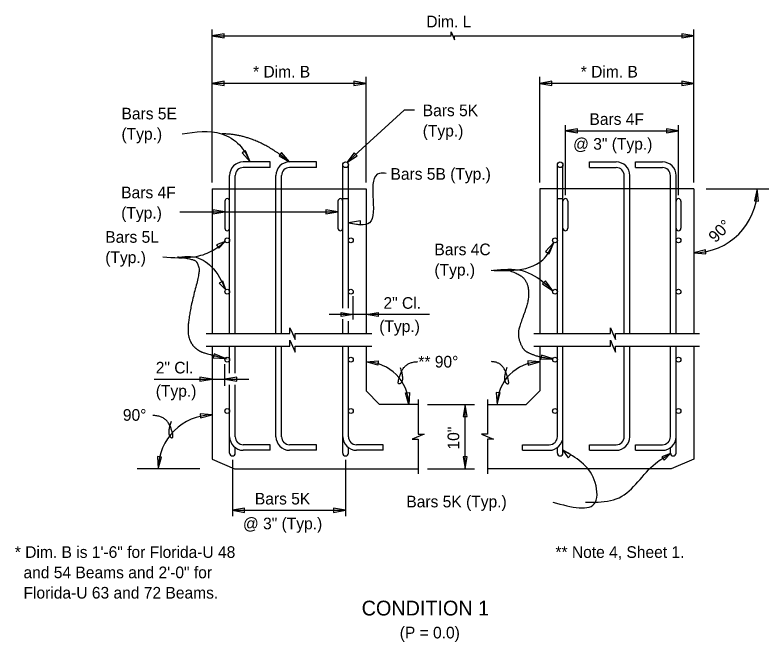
# Model space of a CAD drawing. Extents: x 0.5 to 29.5, y 0.9 to 17.7.
# Drawn here: x 0.5 to 10.29, y 9.57 to 17.7 of the extents above; entities that cross this region are included whole.
import ezdxf

# ---------------------------------------------------------------- set-up
doc = ezdxf.new("R2010")
doc.units = 0
for name, color, linetype in [('BeamConc', 7, 'Continuous'), ('Dimension', 7, 'Continuous'), ('Rebar', 7, 'Continuous'), ('TextStructures', 7, 'Continuous')]:
    doc.layers.add(name, color=color, linetype=linetype)

# ---------------------------------------------------------------- blocks, each defined once
blk = doc.blocks.new('Terminator-Arrow')
at = {"layer": 'Dimension'}
blk.add_lwpolyline([(0, 0), (-0.00041, 0.000069), (-0.00041, -0.000069)], close=True, dxfattribs=at)

msp = doc.modelspace()

# ---------------------------------------------------------------- linework, layer by layer
at = {"layer": 'BeamConc'}
for p, q in [((3.0596, 15.4467), (3.0596, 13.5686)), ((3.0597, 15.4467), (5.0597, 15.4467)), ((5.0597, 15.4467), (5.0597, 13.5686)), ((9.3147, 15.4467), (7.3147, 15.4467)), ((7.3147, 15.4467), (7.3147, 13.5686)), ((9.3146, 15.4467), (9.3146, 13.5686)), ((3.0596, 13.4069), (3.0596, 11.9397)), ((5.0597, 13.4069), (5.0597, 12.8248)), ((7.3147, 13.4069), (7.3147, 12.8248)), ((9.3146, 13.4069), (9.3146, 11.9397)), ((5.2364, 12.648), (5.0597, 12.8248)), ((7.1379, 12.648), (7.3147, 12.8248)), ((5.737, 12.648), (5.2364, 12.648)), ((6.6373, 12.648), (7.1379, 12.648)), ((3.0596, 11.9397), (3.3513, 11.8147)), ((9.3146, 11.9397), (9.023, 11.8147)), ((3.3513, 11.8147), (5.737, 11.8147)), ((9.023, 11.8147), (6.6373, 11.8147))]:
    msp.add_line(p, q, dxfattribs=at)
at = {"layer": 'Dimension'}
for p, q in [((3.0597, 15.5294), (3.0597, 17.5191)), ((3.0597, 15.5294), (3.0597, 17.5191)), ((9.3147, 15.5294), (9.3147, 17.5191)), ((9.3147, 15.5294), (9.3147, 17.5191)), ((5.0597, 15.5294), (5.0597, 16.9032)), ((5.0597, 15.5294), (5.0597, 16.9032)), ((7.3146, 15.5294), (7.3146, 16.9032)), ((7.3146, 15.5294), (7.3146, 16.9032)), ((3.0595, 16.8187), (5.0595, 16.8187)), ((3.0595, 16.8187), (5.0595, 16.8187)), ((7.3146, 16.8187), (9.3146, 16.8187)), ((7.3146, 16.8187), (9.3146, 16.8187)), ((7.648, 15.3678), (7.648, 16.2742)), ((7.648, 15.3678), (7.648, 16.2742)), ((9.1167, 15.3678), (9.1167, 16.2742)), ((9.1167, 15.3678), (9.1167, 16.2742)), ((7.648, 16.2036), (9.1167, 16.2036)), ((7.648, 16.2036), (9.1167, 16.2036)), ((9.4776, 15.4467), (10.2909, 15.4467)), ((9.4776, 15.4467), (10.2909, 15.4467)), ((2.6412, 15.1505), (3.2263, 15.1505)), ((2.6412, 15.1505), (3.2263, 15.1505)), ((3.2263, 15.1505), (4.6951, 15.1505)), ((3.2263, 15.1505), (4.6951, 15.1505)), ((4.893, 13.7541), (4.893, 14.0544)), ((4.893, 13.7541), (4.893, 14.0544)), ((5.8819, 13.8162), (4.5829, 13.8162)), ((5.8819, 13.8162), (4.5829, 13.8162)), ((3.2263, 12.8915), (3.2263, 13.1747)), ((3.2263, 12.8915), (3.2263, 13.1747)), ((2.3102, 12.9769), (3.5364, 12.9769)), ((2.3102, 12.9769), (3.5364, 12.9769)), ((5.8581, 12.648), (6.4662, 12.648)), ((5.8581, 12.648), (6.4662, 12.648)), ((6.3454, 11.8147), (6.3454, 12.648)), ((6.3454, 11.8147), (6.3454, 12.648)), ((3.3253, 11.932), (3.3253, 11.2001)), ((3.3253, 11.932), (3.3253, 11.2001)), ((4.794, 11.932), (4.794, 11.2001)), ((4.794, 11.932), (4.794, 11.2001)), ((2.9018, 11.8147), (2.0885, 11.8147)), ((2.9018, 11.8147), (2.0885, 11.8147)), ((5.8581, 11.8147), (6.4662, 11.8147)), ((5.8581, 11.8147), (6.4662, 11.8147)), ((3.3253, 11.2757), (4.794, 11.2757)), ((3.3253, 11.2757), (4.794, 11.2757))]:
    msp.add_line(p, q, dxfattribs=at)
for points in [[(3.0595, 17.434), (6.1645, 17.434), (6.1645, 17.4857), (6.187, 17.434), (6.2095, 17.3823), (6.2095, 17.434), (9.3145, 17.434)], [(3.0595, 17.434), (6.1645, 17.434), (6.1645, 17.4857), (6.187, 17.434), (6.2095, 17.3823), (6.2095, 17.434), (9.3145, 17.434)], [(5.687, 16.4694), (5.554, 16.4694), (4.8092, 15.7907)], [(5.687, 16.4694), (5.554, 16.4694), (4.8092, 15.7907)], [(2.984, 13.5686), (4.0719, 13.5686), (4.0719, 13.6461), (4.1056, 13.5686), (4.1394, 13.4911), (4.1394, 13.5686), (5.1353, 13.5686)], [(2.984, 13.5686), (4.0719, 13.5686), (4.0719, 13.6461), (4.1056, 13.5686), (4.1394, 13.4911), (4.1394, 13.5686), (5.1353, 13.5686)], [(7.239, 13.5686), (8.2317, 13.5686), (8.2317, 13.6461), (8.2655, 13.5686), (8.2992, 13.4911), (8.2992, 13.5686), (9.3903, 13.5686)], [(7.239, 13.5686), (8.2317, 13.5686), (8.2317, 13.6461), (8.2655, 13.5686), (8.2992, 13.4911), (8.2992, 13.5686), (9.3903, 13.5686)], [(2.984, 13.4069), (4.0719, 13.4069), (4.0719, 13.4844), (4.1056, 13.4069), (4.1394, 13.3294), (4.1394, 13.4069), (5.1353, 13.4069)], [(2.984, 13.4069), (4.0719, 13.4069), (4.0719, 13.4844), (4.1056, 13.4069), (4.1394, 13.3294), (4.1394, 13.4069), (5.1353, 13.4069)], [(7.239, 13.4069), (8.2317, 13.4069), (8.2317, 13.4844), (8.2655, 13.4069), (8.2992, 13.3294), (8.2992, 13.4069), (9.3903, 13.4069)], [(7.239, 13.4069), (8.2317, 13.4069), (8.2317, 13.4844), (8.2655, 13.4069), (8.2992, 13.3294), (8.2992, 13.4069), (9.3903, 13.4069)], [(5.737, 12.7151), (5.737, 12.2651), (5.8145, 12.2651), (5.6595, 12.1976), (5.737, 12.1976), (5.737, 11.7476)], [(5.737, 12.7151), (5.737, 12.2651), (5.8145, 12.2651), (5.6595, 12.1976), (5.737, 12.1976), (5.737, 11.7476)], [(6.6373, 12.7151), (6.6373, 12.2651), (6.5598, 12.2651), (6.7148, 12.1976), (6.6373, 12.1976), (6.6373, 11.7476)], [(6.6373, 12.7151), (6.6373, 12.2651), (6.5598, 12.2651), (6.7148, 12.1976), (6.6373, 12.1976), (6.6373, 11.7476)]]:
    msp.add_lwpolyline(points, dxfattribs=at)
for points in [[(3.5569, 15.7974), (3.4949, 15.9432), (3.4504, 15.9146)], [(3.5569, 15.7974), (3.4949, 15.9432), (3.4504, 15.9146)], [(4.0668, 15.798), (3.9638, 15.9184), (3.9299, 15.8777)], [(4.0668, 15.798), (3.9638, 15.9184), (3.9299, 15.8777)], [(4.8092, 15.7908), (4.9425, 15.8764), (4.9069, 15.9155)], [(4.8092, 15.7908), (4.9425, 15.8764), (4.9069, 15.9155)], [(10.14, 15.4467), (10.1018, 15.293), (10.1546, 15.289)], [(10.14, 15.4467), (10.1018, 15.293), (10.1546, 15.289)], [(3.2263, 15.1505), (3.0701, 15.177), (3.0701, 15.1241)], [(3.2263, 15.1505), (3.0701, 15.177), (3.0701, 15.1241)], [(4.6951, 15.1505), (4.5389, 15.177), (4.5389, 15.1241)], [(4.6951, 15.1505), (4.5389, 15.177), (4.5389, 15.1241)], [(4.8305, 15.0073), (4.9867, 14.9809), (4.9867, 15.0338)], [(4.8305, 15.0073), (4.9867, 14.9809), (4.9867, 15.0338)], [(3.2294, 14.7665), (3.1187, 14.7199), (3.1495, 14.6768)], [(3.2294, 14.7665), (3.1187, 14.7199), (3.1495, 14.6768)], [(7.496, 14.7535), (7.3906, 14.6352), (7.4355, 14.6071)], [(7.496, 14.7535), (7.3906, 14.6352), (7.4355, 14.6071)], [(9.3147, 14.6188), (9.4725, 14.6058), (9.468, 14.6585)], [(9.3147, 14.6188), (9.4725, 14.6058), (9.468, 14.6585)], [(3.238, 14.1377), (3.1988, 14.2512), (3.1538, 14.2233)], [(3.238, 14.1377), (3.1988, 14.2512), (3.1538, 14.2233)], [(7.4844, 14.1268), (7.3891, 14.2534), (7.3528, 14.215)], [(7.4844, 14.1268), (7.3891, 14.2534), (7.3528, 14.215)], [(3.2344, 13.2478), (3.0868, 13.3051), (3.0761, 13.2533)], [(3.2344, 13.2478), (3.0868, 13.3051), (3.0761, 13.2533)], [(5.0597, 13.2014), (5.2175, 13.2145), (5.213, 13.1617)], [(5.0597, 13.2014), (5.2175, 13.2145), (5.213, 13.1617)], [(7.3168, 13.2014), (7.1589, 13.2145), (7.1634, 13.1617)], [(7.3168, 13.2014), (7.1589, 13.2145), (7.1634, 13.1617)], [(7.4882, 13.2403), (7.3371, 13.2881), (7.3299, 13.2356)], [(7.4882, 13.2403), (7.3371, 13.2881), (7.3299, 13.2356)], [(5.6144, 12.6461), (5.5733, 12.7991), (5.626, 12.8041)], [(5.6144, 12.6461), (5.5733, 12.7991), (5.626, 12.8041)], [(6.762, 12.6461), (6.8032, 12.7991), (6.7505, 12.8041)], [(6.762, 12.6461), (6.8032, 12.7991), (6.7505, 12.8041)], [(6.3454, 12.648), (6.319, 12.4918), (6.3719, 12.4918)], [(6.3454, 12.648), (6.319, 12.4918), (6.3719, 12.4918)], [(3.0617, 12.5144), (2.9039, 12.5275), (2.9084, 12.4748)], [(3.0617, 12.5144), (2.9039, 12.5275), (2.9084, 12.4748)], [(7.6167, 12.0573), (7.6836, 11.9576), (7.72, 11.996)], [(7.6167, 12.0573), (7.6836, 11.9576), (7.72, 11.996)], [(2.3623, 11.8144), (2.4034, 11.9674), (2.3507, 11.9724)], [(2.3623, 11.8144), (2.4034, 11.9674), (2.3507, 11.9724)], [(6.3454, 11.8147), (6.3719, 11.9709), (6.319, 11.9709)], [(6.3454, 11.8147), (6.3719, 11.9709), (6.319, 11.9709)], [(9.0132, 12.0113), (8.9006, 11.9696), (8.9294, 11.9252)], [(9.0132, 12.0113), (8.9006, 11.9696), (8.9294, 11.9252)]]:
    msp.add_lwpolyline(points, close=True, dxfattribs=at)
for centre, radius, start, end in [((9.3121, 15.4467), 0.8279, 270.17686, 0), ((9.3121, 15.4467), 0.8279, 270.17686, 0), ((5.0553, 12.6422), 0.5592, 0.39914, 89.54996), ((5.0553, 12.6422), 0.5592, 0.39914, 89.54996), ((7.3212, 12.6422), 0.5592, 90.45004, 179.60086), ((7.3212, 12.6422), 0.5592, 90.45004, 179.60086), ((3.0673, 11.8094), 0.705, 90.45004, 179.60086), ((3.0673, 11.8094), 0.705, 90.45004, 179.60086)]:
    msp.add_arc(centre, radius, start, end, dxfattribs=at)
for points in [[(2.67, 16.162), (3.1844, 16.162), (3.4145, 16.0195), (3.5569, 15.7974)], [(2.67, 16.162), (3.1844, 16.162), (3.4145, 16.0195), (3.5569, 15.7974)], [(5.3202, 15.6496), (5.2362, 15.6496), (5.1038, 15.0073), (4.8305, 15.0073)], [(5.3202, 15.6496), (5.2362, 15.6496), (5.1038, 15.0073), (4.8305, 15.0073)], [(2.4221, 14.5672), (2.831, 14.5672), (3.0502, 14.6385), (3.2294, 14.7665)], [(2.4221, 14.5672), (2.831, 14.5672), (3.0502, 14.6385), (3.2294, 14.7665)], [(6.686, 14.3917), (6.9806, 14.3917), (7.3535, 14.526), (7.496, 14.7535)], [(6.686, 14.3917), (6.9806, 14.3917), (7.3535, 14.526), (7.496, 14.7535)], [(2.6667, 14.5672), (2.8201, 14.5672), (3.0502, 14.4411), (3.238, 14.1377)], [(2.6667, 14.5672), (2.8201, 14.5672), (3.0502, 14.4411), (3.238, 14.1377)], [(6.7146, 14.3917), (7.085, 14.3867), (7.3858, 14.2201), (7.4844, 14.1268)], [(6.7146, 14.3917), (7.085, 14.3867), (7.3858, 14.2201), (7.4844, 14.1268)], [(7.4869, 11.3802), (8.0377, 11.3809), (8.023, 11.6725), (7.6167, 12.0573)], [(7.4869, 11.3802), (8.0377, 11.3809), (8.023, 11.6725), (7.6167, 12.0573)], [(7.9078, 11.3808), (8.0326, 11.3809), (8.3444, 11.4388), (8.8193, 11.8852), (9.0132, 12.0112)], [(7.9078, 11.3808), (8.0326, 11.3809), (8.3444, 11.4388), (8.8193, 11.8852), (9.0132, 12.0112)]]:
    msp.add_spline(points, degree=3, dxfattribs=at)
for points in [[(4.0669, 15.7974), (3.6296, 16.1619), (3.1923, 16.1619)], [(4.0669, 15.7974), (3.6296, 16.1619), (3.1923, 16.1619)], [(2.6102, 14.5672), (2.8249, 14.5347), (2.8713, 14.4882), (2.9054, 14.3766), (2.7877, 13.952), (2.735, 13.5893), (2.7877, 13.4344), (2.8899, 13.3414), (3.0045, 13.3042), (3.2556, 13.2403)], [(2.6102, 14.5672), (2.8249, 14.5347), (2.8713, 14.4882), (2.9054, 14.3766), (2.7877, 13.952), (2.735, 13.5893), (2.7877, 13.4344), (2.8899, 13.3414), (3.0045, 13.3042), (3.2556, 13.2403)], [(6.9141, 14.389), (7.0804, 14.3358), (7.1708, 14.193), (7.1708, 13.9885), (7.0757, 13.7316), (7.0234, 13.5603), (7.0852, 13.3842), (7.147, 13.3272), (7.3087, 13.2653), (7.4882, 13.2403)], [(6.9141, 14.389), (7.0804, 14.3358), (7.1708, 14.193), (7.1708, 13.9885), (7.0757, 13.7316), (7.0234, 13.5603), (7.0852, 13.3842), (7.147, 13.3272), (7.3087, 13.2653), (7.4882, 13.2403)], [(5.5035, 13.1287), (5.5608, 12.9568), (5.45, 12.8881), (5.5627, 13.2051), (5.7343, 13.2051)], [(5.5035, 13.1287), (5.5608, 12.9568), (5.45, 12.8881), (5.5627, 13.2051), (5.7343, 13.2051)], [(6.8868, 13.1287), (6.8295, 12.9568), (6.9403, 12.8881), (6.8276, 13.2051), (6.688, 13.2051)], [(6.8868, 13.1287), (6.8295, 12.9568), (6.9403, 12.8881), (6.8276, 13.2051), (6.688, 13.2051)], [(2.5274, 12.4294), (2.4701, 12.2575), (2.5808, 12.1887), (2.4682, 12.5058), (2.2906, 12.5058)], [(2.5274, 12.4294), (2.4701, 12.2575), (2.5808, 12.1887), (2.4682, 12.5058), (2.2906, 12.5058)]]:
    msp.add_open_spline(points, degree=2, dxfattribs=at)
at = {"layer": 'Rebar'}
for p, q in [((3.8138, 15.7974), (3.466, 15.7974)), ((3.8138, 15.7245), (3.8138, 15.7974)), ((4.4148, 15.7974), (4.0669, 15.7974)), ((4.4148, 15.7245), (4.4148, 15.7974)), ((4.7576, 13.9017), (4.7576, 15.7609)), ((4.8305, 13.9017), (4.8305, 15.7609)), ((7.5438, 13.5686), (7.5438, 15.7609)), ((7.6167, 13.5686), (7.6167, 15.7609)), ((7.9604, 15.7974), (8.3083, 15.7974)), ((7.9604, 15.7245), (7.9604, 15.7974)), ((8.5605, 15.7974), (8.9084, 15.7974)), ((8.5605, 15.7245), (8.5605, 15.7974)), ((3.8138, 15.7245), (3.466, 15.7245)), ((4.4148, 15.7245), (4.0669, 15.7245)), ((7.9604, 15.7245), (8.3083, 15.7245)), ((8.5605, 15.7245), (8.9084, 15.7245)), ((3.2888, 13.5686), (3.2888, 15.6203)), ((3.3618, 13.5686), (3.3618, 15.6203)), ((3.8898, 13.5686), (3.8898, 15.6203)), ((3.9627, 13.5686), (3.9627, 15.6203)), ((8.4125, 13.5686), (8.4125, 15.6203)), ((8.4854, 13.5686), (8.4854, 15.6203)), ((9.0126, 13.5686), (9.0126, 15.6203)), ((9.0855, 13.5686), (9.0855, 15.6203)), ((3.2263, 15.2904), (3.2263, 14.9363)), ((4.6951, 15.2904), (4.6951, 14.9363)), ((4.7576, 15.3217), (4.8305, 15.3217)), ((7.5438, 15.3217), (7.6167, 15.3217)), ((7.6792, 15.2904), (7.6792, 14.9363)), ((9.148, 15.2904), (9.148, 14.9363)), ((4.7576, 13.5686), (4.7576, 13.755)), ((4.8305, 13.5686), (4.8305, 13.7326)), ((3.2888, 13.056), (3.2888, 13.4069)), ((3.3618, 13.056), (3.3618, 13.4069)), ((3.8898, 12.2313), (3.8898, 13.4069)), ((3.9627, 12.2314), (3.9627, 13.4069)), ((4.7576, 12.0178), (4.7576, 13.4069)), ((4.8305, 12.2313), (4.8305, 13.4069)), ((7.5438, 12.2313), (7.5438, 13.4069)), ((7.6167, 12.0178), (7.6167, 13.4069)), ((8.4125, 12.2314), (8.4125, 13.4069)), ((8.4854, 12.2313), (8.4854, 13.4069)), ((9.0126, 12.2313), (9.0126, 13.4069)), ((9.0855, 12.0178), (9.0855, 13.4069)), ((3.2888, 12.0178), (3.2888, 12.9035)), ((3.3618, 12.2313), (3.3618, 12.9035)), ((3.3618, 12.0178), (3.3618, 12.0881)), ((3.8138, 12.1271), (3.466, 12.1271)), ((3.8138, 12.0542), (3.466, 12.0542)), ((3.8138, 12.0542), (3.8138, 12.1271)), ((4.4148, 12.1271), (4.0669, 12.1271)), ((4.4148, 12.0542), (4.0669, 12.0542)), ((4.4148, 12.0542), (4.4148, 12.1271)), ((4.8305, 12.0178), (4.8305, 12.0881)), ((5.2826, 12.1271), (4.9347, 12.1271)), ((5.2826, 12.0542), (4.9347, 12.0542)), ((5.2826, 12.0542), (5.2826, 12.1271)), ((7.0917, 12.1271), (7.4396, 12.1271)), ((7.0917, 12.0542), (7.0917, 12.1271)), ((7.0917, 12.0542), (7.4396, 12.0542)), ((7.5438, 12.0178), (7.5438, 12.0881)), ((7.9604, 12.1271), (8.3083, 12.1271)), ((7.9604, 12.0542), (7.9604, 12.1271)), ((7.9604, 12.0542), (8.3083, 12.0542)), ((8.5605, 12.1271), (8.9084, 12.1271)), ((8.5605, 12.0542), (8.5605, 12.1271)), ((8.5605, 12.0542), (8.9084, 12.0542)), ((9.0126, 12.0178), (9.0126, 12.0881))]:
    msp.add_line(p, q, dxfattribs=at)
for centre, radius in [((4.794, 15.7609), 0.0365), ((7.5803, 15.7609), 0.0365), ((3.2576, 14.78), 0.0312), ((4.8618, 14.78), 0.0312), ((7.5126, 14.78), 0.0312), ((9.1167, 14.78), 0.0312), ((3.2576, 14.1133), 0.0312), ((4.8618, 14.1133), 0.0312), ((7.5126, 14.1133), 0.0312), ((9.1167, 14.1133), 0.0312), ((3.2576, 13.2313), 0.0312), ((4.8618, 13.2313), 0.0312), ((7.5126, 13.2313), 0.0312), ((9.1167, 13.2313), 0.0312), ((3.2576, 12.5646), 0.0312), ((4.8618, 12.5646), 0.0312), ((7.5126, 12.5646), 0.0312), ((9.1167, 12.5646), 0.0312)]:
    msp.add_circle(centre, radius, dxfattribs=at)
for centre, radius, start, end in [((3.466, 15.6203), 0.1771, 90, 180), ((4.0669, 15.6203), 0.1771, 90, 180), ((8.3083, 15.6203), 0.1771, 0, 90), ((8.9084, 15.6203), 0.1771, 0, 90), ((3.466, 15.6203), 0.1042, 90, 180), ((4.0669, 15.6203), 0.1042, 90, 180), ((8.3083, 15.6203), 0.1042, 0, 90), ((8.9084, 15.6203), 0.1042, 0, 90), ((3.2576, 15.2904), 0.0312, 0, 180), ((4.7263, 15.2904), 0.0312, 0, 180), ((7.648, 15.2904), 0.0312, 0, 180), ((9.1167, 15.2904), 0.0312, 0, 180), ((3.2576, 14.9363), 0.0312, 180, 0), ((4.7263, 14.9363), 0.0312, 180, 0), ((7.648, 14.9363), 0.0312, 180, 0), ((9.1167, 14.9363), 0.0312, 180, 0), ((3.466, 12.2313), 0.1771, 180, 270), ((3.466, 12.2313), 0.1042, 180, 270), ((4.0669, 12.2313), 0.1771, 180, 270), ((4.0669, 12.2313), 0.1042, 180, 270), ((4.9347, 12.2313), 0.1771, 180, 270), ((4.9347, 12.2313), 0.1042, 180, 270), ((7.4396, 12.2313), 0.1042, 270, 360), ((7.4396, 12.2313), 0.1771, 270, 360), ((8.3083, 12.2313), 0.1042, 270, 0), ((8.3083, 12.2313), 0.1771, 270, 0), ((8.9084, 12.2313), 0.1042, 270, 360), ((8.9084, 12.2313), 0.1771, 270, 360), ((3.3253, 12.0178), 0.0365, 180, 0), ((4.794, 12.0178), 0.0365, 180, 0), ((7.5803, 12.0178), 0.0365, 180, 0), ((9.049, 12.0178), 0.0365, 180, 0)]:
    msp.add_arc(centre, radius, start, end, dxfattribs=at)

# ---------------------------------------------------------------- block references
at = {"layer": 'Dimension', "xscale": 381, "rotation": 180}
for p, yscale in [((3.0594, 17.4335), 384.0238095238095), ((3.0594, 17.4335), 384.0238095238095), ((3.0594, 16.8183), 384.0238095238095), ((3.0594, 16.8183), 384.0238095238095), ((7.3144, 16.8183), 384.0238095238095), ((7.3144, 16.8183), 384.0238095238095), ((7.6478, 16.2033), 384.0238095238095), ((7.6478, 16.2033), 384.0238095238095), ((5.0596, 13.8159), -384.0238095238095), ((5.0596, 13.8159), -384.0238095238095), ((3.2262, 12.9764), 384.0238095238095), ((3.2262, 12.9764), 384.0238095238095), ((3.3252, 11.2754), 384.0238095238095), ((3.3252, 11.2754), 384.0238095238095)]:
    msp.add_blockref('Terminator-Arrow', p, dxfattribs=dict(at, yscale=yscale))
at = {"layer": 'Dimension', "xscale": 381}
for p, yscale in [((9.3144, 17.4336), 384.0238095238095), ((9.3144, 17.4336), 384.0238095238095), ((5.0594, 16.8183), 384.0238095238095), ((5.0594, 16.8183), 384.0238095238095), ((9.3144, 16.8183), 384.0238095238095), ((9.3144, 16.8183), 384.0238095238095), ((9.1166, 16.2033), 384.0238095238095), ((9.1166, 16.2033), 384.0238095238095), ((4.8929, 13.8159), -384.0238095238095), ((4.8929, 13.8159), -384.0238095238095), ((3.0596, 12.9764), 384.0238095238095), ((3.0596, 12.9764), 384.0238095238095), ((4.7939, 11.2754), 384.0238095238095), ((4.7939, 11.2754), 384.0238095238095)]:
    msp.add_blockref('Terminator-Arrow', p, dxfattribs=dict(at, yscale=yscale))

# ---------------------------------------------------------------- texts
at = {"layer": 'Dimension'}
for s, p in [('Bars 5K', (5.7957, 16.3918)), ('Bars 5E', (1.8842, 16.3502)), ('(Typ.)', (5.7957, 16.1278)), ('(Typ.)', (1.8842, 16.0862)), ('Bars 4F', (1.8807, 15.3266)), ('(Typ.)', (1.8807, 15.0626)), ('Bars 5L', (1.6736, 14.7485)), ('Bars 4C', (5.9475, 14.5869)), ('(Typ.)', (1.6736, 14.4845)), ('(Typ.)', (5.9475, 14.3229)), ('* Dim. B is 1\'-6" for Florida-U 48', (0.4993, 10.6577)), ('** Note 4, Sheet 1.', (7.5192, 10.6577)), ('  and 54 Beams and 2\'-0" for ', (0.4993, 10.3937)), ('  Florida-U 63 and 72 Beams.', (0.4993, 10.1297))]:
    msp.add_text(s, height=0.1512, dxfattribs=at).set_placement(p)
at = {"layer": 'TextStructures'}
for s, height, p in [('Dim. L', 0.1512, (5.8422, 17.5452)), ('* Dim. B', 0.1512, (3.5927, 16.8939)), ('* Dim. B', 0.1512, (7.8477, 16.8939)), ('Bars 4F', 0.1512, (7.9605, 16.2789)), ('@ 3" (Typ.)', 0.1512, (7.7483, 15.9568)), ('Bars 5B (Typ.)', 0.1512, (5.3769, 15.5667)), ('2" Cl.', 0.1512, (5.286, 13.8915)), ('(Typ.)', 0.1512, (5.2312, 13.5891)), ('** 90°', 0.1512, (5.7389, 13.1291)), ('2" Cl.', 0.1512, (2.3292, 13.052)), ('(Typ.)', 0.1512, (2.3292, 12.7496)), ('90°', 0.1512, (1.9023, 12.4381)), ('Bars 5K', 0.1512, (3.6161, 11.351)), ('Bars 5K (Typ.)', 0.1512, (5.583, 11.3135)), ('@ 3" (Typ.)', 0.1512, (3.4612, 11.0287)), ('CONDITION 1', 0.192, (5.003, 9.91)), ('(P = 0.0)', 0.1512, (5.4968, 9.6123))]:
    msp.add_text(s, height=height, dxfattribs=at).set_placement(p)
for s, rotation, p in [(' 90°', 45, (9.5573, 14.701)), ('10"', 90, (6.2698, 12.0644))]:
    msp.add_text(s, height=0.1512, rotation=rotation, dxfattribs=at).set_placement(p)

doc.saveas('drawing.dxf')
